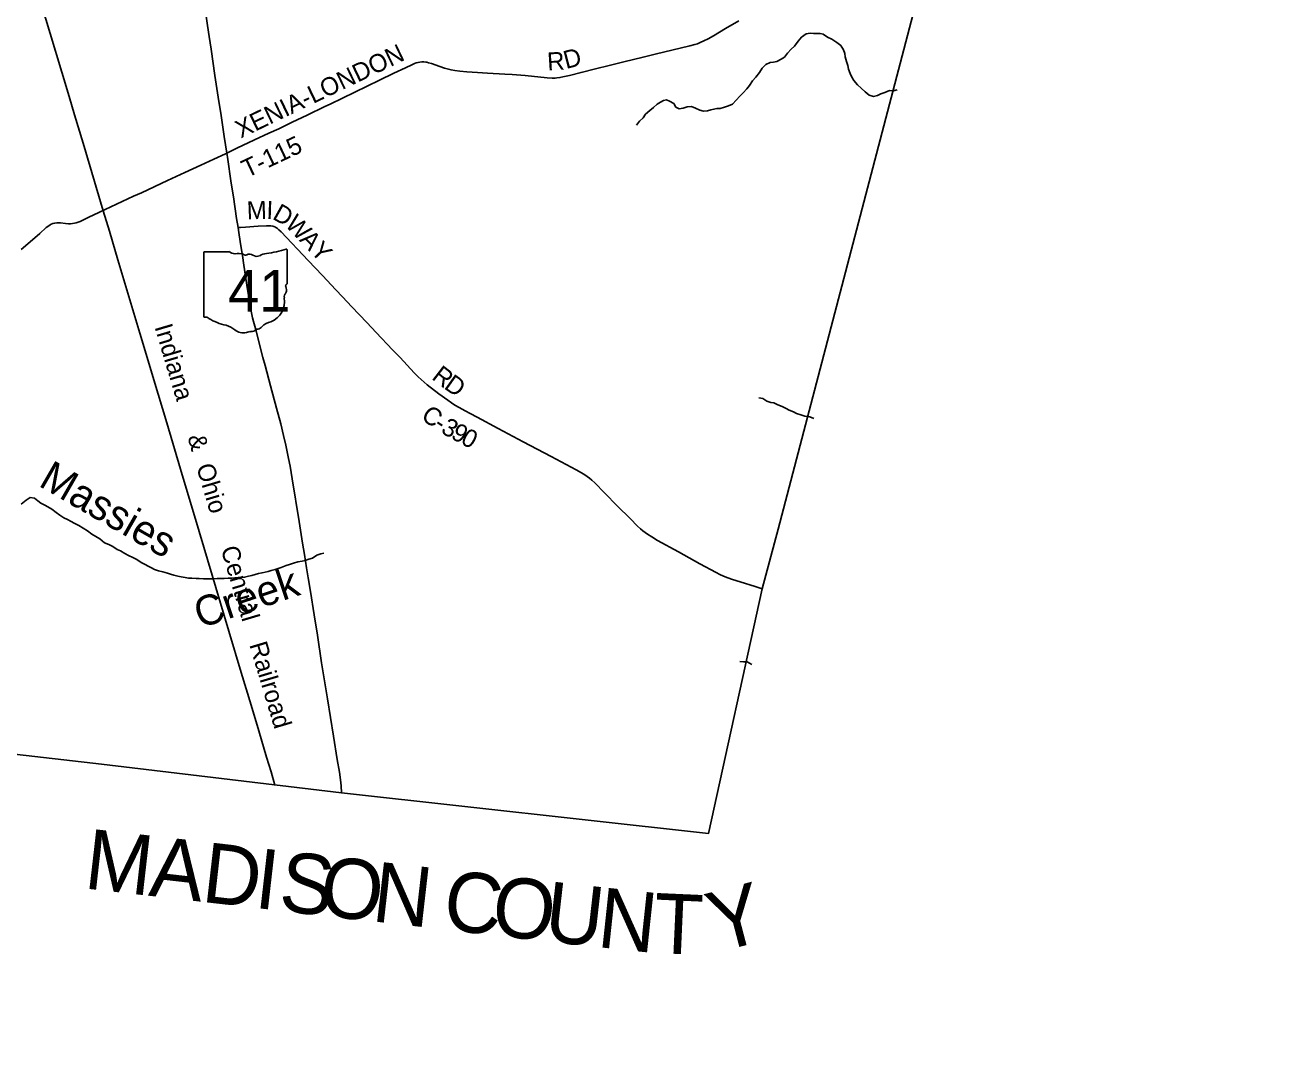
# Model space of a CAD drawing. Extents: x 1410790 to 1770854, y 566777 to 831614.
# Drawn here: x 1651013 to 1671974, y 642079 to 659329 of the extents above; entities that cross this region are included whole.
import ezdxf

# ---------------------------------------------------------------- set-up
doc = ezdxf.new("R2010")
doc.units = 0
for name, color, linetype in [('GM_X_Adjacent_County', 7, 'Continuous'), ('GM_X_Adjacent_County_Text', 7, 'Continuous'), ('GM_X_County', 7, 'Continuous'), ('GM_X_County_Road', 7, 'Continuous'), ('GM_X_County_Road_Text', 7, 'Continuous'), ('GM_X_Minor_River', 7, 'Continuous'), ('GM_X_Minor_River_Text', 7, 'Continuous'), ('GM_X_Rail_Line', 7, 'Continuous'), ('GM_X_Rail_Line_Text', 7, 'Continuous'), ('GM_X_State_Location', 7, 'Continuous'), ('GM_X_State_Route', 7, 'Continuous'), ('GM_X_State_Shield', 7, 'Continuous'), ('GM_X_Township', 7, 'Continuous'), ('GM_X_Township_Road', 7, 'Continuous'), ('GM_X_Township_Road_Text', 7, 'Continuous')]:
    doc.layers.add(name, color=color, linetype=linetype)

msp = doc.modelspace()

# ---------------------------------------------------------------- linework, layer by layer
at = {"layer": 'GM_X_Adjacent_County'}
msp.add_lwpolyline([(1671974, 683181), (1671693, 682151), (1669822, 675181), (1669783, 675026), (1667943, 667921), (1667581, 666498), (1666885, 663874), (1666084, 660564), (1663561, 650929), (1663296, 649933), (1662403, 645855), (1656287, 646528), (1652288, 647008), (1645905, 647740), (1645710, 645966), (1645124, 639449)], dxfattribs=at)
at = {"layer": 'GM_X_County'}
msp.add_lwpolyline([(1671974, 683181), (1671693, 682151), (1669822, 675181), (1669783, 675026), (1667943, 667921), (1667581, 666498), (1666885, 663874), (1666084, 660564), (1663561, 650929), (1663296, 649933), (1662403, 645855), (1656287, 646528), (1652288, 647008), (1645905, 647740), (1646054, 648559), (1644155, 648666), (1640422, 649068), (1640009, 649114), (1636122, 649546)], dxfattribs=at)
at = {"layer": 'GM_X_County_Road'}
msp.add_lwpolyline([(1654561, 655954), (1654601, 655957), (1654683, 655963), (1654897, 655975), (1655035, 655981), (1655081, 655984), (1655110, 655983), (1655143, 655977), (1655159, 655972), (1655174, 655966), (1655189, 655958), (1655203, 655950), (1655217, 655940), (1655242, 655918), (1655278, 655882), (1655729, 655407), (1655966, 655157), (1656191, 654918), (1656300, 654801), (1656459, 654634), (1656707, 654372), (1656865, 654204), (1657134, 653918), (1657261, 653786), (1657497, 653535), (1657565, 653464), (1657612, 653419), (1657661, 653375), (1657711, 653334), (1657907, 653185), (1658056, 653075), (1658118, 653030), (1658173, 652994), (1658244, 652953), (1658344, 652898), (1658431, 652852), (1658547, 652791), (1658896, 652607), (1659315, 652383), (1659778, 652136), (1660199, 651914), (1660286, 651866), (1660341, 651832), (1660382, 651804), (1660421, 651774), (1660459, 651741), (1660507, 651696), (1660669, 651534), (1660887, 651311), (1661096, 651102), (1661221, 650975), (1661269, 650930), (1661308, 650898), (1661347, 650869), (1661387, 650841), (1661457, 650797), (1661554, 650740), (1661900, 650549), (1662259, 650351), (1662530, 650202), (1662589, 650172), (1662653, 650144), (1662727, 650115), (1662804, 650087), (1662929, 650048), (1663179, 649969), (1663296, 649933)], dxfattribs=at)
at = {"layer": 'GM_X_Minor_River'}
for points in [[(1665544, 658249), (1665483, 658236), (1665417, 658237), (1665342, 658207), (1665272, 658182), (1665216, 658158), (1665150, 658142), (1665082, 658159), (1665012, 658215), (1664946, 658278), (1664885, 658336), (1664825, 658406), (1664783, 658471), (1664764, 658523), (1664738, 658595), (1664726, 658655), (1664703, 658724), (1664681, 658802), (1664672, 658856), (1664654, 658918), (1664608, 658989), (1664541, 659037), (1664455, 659094), (1664387, 659130), (1664315, 659177), (1664261, 659187), (1664201, 659187), (1664151, 659190), (1664099, 659194), (1664029, 659184), (1663950, 659127), (1663896, 659061), (1663833, 658981), (1663781, 658931), (1663718, 658862), (1663668, 658794), (1663614, 658760), (1663539, 658722), (1663485, 658713), (1663431, 658705), (1663355, 658671), (1663298, 658609), (1663252, 658540), (1663189, 658464), (1663133, 658402), (1663086, 658320), (1663042, 658266), (1662981, 658198), (1662927, 658147), (1662862, 658077), (1662800, 658011), (1662734, 657981), (1662671, 657960), (1662595, 657938), (1662543, 657938), (1662491, 657927), (1662441, 657917), (1662387, 657903), (1662317, 657893), (1662255, 657912), (1662187, 657946), (1662121, 657973), (1662049, 657965), (1661978, 657947), (1661914, 657934), (1661860, 657962), (1661827, 658022), (1661753, 658061), (1661701, 658081), (1661651, 658074), (1661601, 658046), (1661548, 658010), (1661488, 657958), (1661426, 657904), (1661353, 657843), (1661311, 657783), (1661250, 657727), (1661204, 657663)], [(1664160, 652770), (1664090, 652798), (1664007, 652808), (1663939, 652834), (1663869, 652853), (1663817, 652883), (1663749, 652911), (1663695, 652940), (1663627, 652972), (1663555, 652999), (1663490, 653031), (1663440, 653037), (1663376, 653058), (1663306, 653104), (1663242, 653113)], [(1650945, 651342), (1651028, 651411), (1651097, 651454), (1651167, 651442), (1651223, 651397), (1651274, 651360), (1651350, 651322), (1651458, 651261), (1651532, 651206), (1651593, 651161), (1651657, 651116), (1651717, 651088), (1651779, 651053), (1651832, 651024), (1651910, 650988), (1651980, 650943), (1652052, 650898)], [(1652052, 650898), (1652123, 650843), (1652191, 650805), (1652255, 650764), (1652337, 650700)], [(1652337, 650700), (1652405, 650671), (1652475, 650635), (1652549, 650590), (1652601, 650564), (1652673, 650520), (1652738, 650485), (1652806, 650453), (1652876, 650418), (1652946, 650370), (1653012, 650338), (1653066, 650307), (1653120, 650279), (1653171, 650255), (1653233, 650234), (1653309, 650214), (1653383, 650191), (1653437, 650175), (1653489, 650157), (1653555, 650144), (1653611, 650132), (1653681, 650118), (1653735, 650109), (1653789, 650107), (1653861, 650106), (1653913, 650104), (1653986, 650100), (1654058, 650097), (1654108, 650099), (1654162, 650101), (1654214, 650103), (1654272, 650102), (1654330, 650104), (1654394, 650108), (1654456, 650111), (1654508, 650117), (1654564, 650119), (1654614, 650122), (1654671, 650126), (1654737, 650142), (1654793, 650153), (1654901, 650185), (1654961, 650200), (1655011, 650210), (1655062, 650222), (1655112, 650238), (1655178, 650253), (1655230, 650271), (1655280, 650287), (1655363, 650318), (1655417, 650338), (1655483, 650360), (1655555, 650379), (1655629, 650391), (1655680, 650405), (1655740, 650424), (1655804, 650442), (1655874, 650494), (1655943, 650515), (1655993, 650525)], [(1663123, 648672), (1663046, 648717), (1662984, 648714), (1662924, 648720)]]:
    msp.add_lwpolyline(points, dxfattribs=at)
at = {"layer": 'GM_X_Rail_Line'}
msp.add_lwpolyline([(1655177, 646661), (1655111, 646880), (1655038, 647123), (1654906, 647565), (1654778, 647992), (1654616, 648536), (1654410, 649227), (1653914, 650885), (1653603, 651924), (1653373, 652700), (1653229, 653178), (1652926, 654192), (1652560, 655418), (1652417, 655892), (1652314, 656236), (1651979, 657361), (1651838, 657833), (1651745, 658140), (1651625, 658543), (1651432, 659188), (1651215, 659914)], dxfattribs=at)
at = {"layer": 'GM_X_State_Route'}
msp.add_lwpolyline([(1656287, 646528), (1656278, 646649), (1656268, 646747), (1656250, 646877), (1656215, 647088), (1656152, 647477), (1656102, 647787), (1656052, 648096), (1656004, 648396), (1655954, 648699), (1655883, 649159), (1655829, 649500), (1655766, 649888), (1655730, 650115), (1655702, 650279), (1655668, 650503), (1655637, 650695), (1655578, 651054), (1655464, 651766), (1655429, 651976), (1655404, 652105), (1655356, 652328), (1655319, 652488), (1655272, 652680), (1655200, 652945), (1655102, 653314), (1655012, 653655), (1654977, 653786), (1654902, 654070), (1654861, 654233), (1654818, 654389), (1654802, 654452), (1654783, 654534), (1654769, 654613), (1654750, 654729), (1654719, 654924), (1654658, 655329), (1654633, 655491), (1654602, 655685), (1654567, 655912), (1654561, 655954), (1654537, 656107), (1654485, 656464), (1654449, 656693), (1654385, 657129), (1654374, 657194), (1654330, 657475), (1654278, 657823), (1654232, 658129), (1654177, 658491), (1654111, 658931), (1654080, 659139), (1654051, 659321), (1654011, 659593)], dxfattribs=at)
at = {"layer": 'GM_X_State_Shield'}
for p, q in [((1653989, 655534), (1653989, 654477)), ((1654410, 655552), (1654003, 655552)), ((1655381, 655025), (1655381, 655578)), ((1655381, 655025), (1655381, 655025))]:
    msp.add_line(p, q, dxfattribs=at)
for centre, radius, start, end in [((1654005, 655536), 16.1, 98.1301, 188.1301), ((1654508, 655675), 156, 231.6195, 271.1119), ((1654559, 654959), 562, 80.4867, 94.9883), ((1654687, 655541), 45.1, 219.7921, 297.1024), ((1654753, 655419), 93.8, 54.4667, 119.1411), ((1654874, 655587), 113, 233.8562, 294.8282), ((1655074, 655229), 297, 97.3462, 120.7689), ((1654885, 656992), 1476, 275.8445, 288.9065), ((1655366, 655580), 15.5, 351.8621, 97.738), ((1655437, 654794), 105, 136.8065, 186.9296), ((1655378, 654985), 24, 107.944, 210.337), ((1655225, 654915), 144, 340.033, 23.6496), ((1655365, 655023), 16.6, 289.6038, 7.7341), ((1654968, 654724), 369, 292.3089, 8.9858), ((1654005, 654475), 16.3, 171.9584, 258.3066), ((1654008, 654583), 124, 267.339, 280.6039), ((1654033, 654416), 44.8, 29.7484, 93.2717), ((1654598, 655365), 1066, 240.4129, 257.1985), ((1654280, 654002), 334, 47.1842, 75.836), ((1654641, 654411), 212, 230.7004, 286.2918), ((1654764, 654045), 174, 85.6951, 111.2099), ((1654779, 654332), 113, 268.777, 315.5493), ((1654881, 654229), 31.8, 65.7517, 132.6484), ((1654867, 654375), 119, 282.8732, 323.2771), ((1655124, 654180), 202, 94.4031, 142.5768)]:
    msp.add_arc(centre, radius, start, end, dxfattribs=at)
at = {"layer": 'GM_X_Township'}
msp.add_lwpolyline([(1636122, 649546), (1640009, 649114), (1640422, 649068), (1644155, 648666), (1646054, 648559), (1645905, 647740), (1652288, 647008), (1656287, 646528), (1662403, 645855), (1663296, 649933), (1663561, 650929), (1666084, 660564), (1666885, 663874), (1667581, 666498), (1667943, 667921), (1669783, 675026), (1669822, 675181), (1659011, 676224), (1657686, 676331), (1656836, 676404), (1649879, 677009), (1644674, 677520), (1639318, 678094), (1633970, 678678)], dxfattribs=at)
at = {"layer": 'GM_X_Township_Road'}
for points in [[(1654374, 657194), (1654540, 657278), (1654837, 657416), (1655075, 657527), (1655239, 657603), (1655461, 657709), (1655712, 657828), (1656008, 657971), (1656096, 658014), (1656303, 658114), (1656510, 658213), (1656919, 658411), (1657160, 658526), (1657351, 658619), (1657455, 658669), (1657500, 658688), (1657530, 658699), (1657561, 658708), (1657593, 658714), (1657625, 658717), (1657657, 658717), (1657689, 658714), (1657705, 658711), (1657737, 658703), (1657783, 658688), (1657922, 658638), (1658000, 658611), (1658047, 658598), (1658111, 658582), (1658176, 658571), (1658258, 658562), (1658372, 658552), (1658552, 658540), (1658717, 658531), (1659005, 658512), (1659131, 658504), (1659348, 658489), (1659712, 658453), (1659794, 658447), (1659844, 658447), (1659877, 658449), (1659926, 658456), (1659974, 658465), (1660086, 658492), (1660279, 658541), (1660516, 658598), (1660748, 658658), (1660990, 658717), (1661311, 658796), (1661534, 658850), (1661789, 658911), (1662089, 658982), (1662172, 659004), (1662219, 659020), (1662265, 659038), (1662325, 659065), (1662398, 659103), (1662484, 659151), (1662688, 659273), (1662907, 659401)], [(1650946, 655588), (1651095, 655717), (1651255, 655858), (1651366, 655955), (1651405, 655985), (1651432, 656002), (1651446, 656010), (1651476, 656022), (1651507, 656030), (1651539, 656033), (1651555, 656034), (1651604, 656032), (1651685, 656023), (1651735, 656019), (1651768, 656019), (1651801, 656021), (1651834, 656027), (1651866, 656035), (1651897, 656045), (1651928, 656058), (1652077, 656128), (1652240, 656205), (1652344, 656254), (1652537, 656344), (1652819, 656475), (1652954, 656536), (1653387, 656739), (1653674, 656870), (1653943, 656996), (1654160, 657095), (1654354, 657185), (1654374, 657194)]]:
    msp.add_lwpolyline(points, dxfattribs=at)

# ---------------------------------------------------------------- texts
at = {"layer": 'GM_X_Adjacent_County_Text'}
for s, rotation, p in [('M', 353.4754, (1651976, 644940)), ('A', 353.4752, (1653056, 644817)), ('D', 353.4757, (1653934, 644716)), ('I', 353.4746, (1654813, 644616)), ('S', 353.4756, (1655219, 644569)), ('O', 353.4752, (1655893, 644492)), ('N', 353.4754, (1656771, 644392)), ('C', 353.4751, (1657952, 644257)), ('O', 353.4752, (1658760, 644164)), ('U', 353.4782, (1659639, 644064)), ('Y', 14.6545, (1662545, 643864)), ('N', 353.9084, (1660526, 643962)), ('T', 357.4284, (1661472, 643863))]:
    msp.add_text(s, height=1000, rotation=rotation, dxfattribs=at).set_placement(p)
at = {"layer": 'GM_X_County_Road_Text'}
for s, rotation, p in [('M', 2.26, (1654712, 656088)), ('I', 358.0989, (1655031, 656100)), ('D', 330.852, (1655118, 656106)), ('W', 313.8046, (1655330, 655992)), ('A', 313.6463, (1655571, 655741)), ('Y', 313.6463, (1655753, 655550)), ('R', 322.3417, (1657774, 653439)), ('D', 324.7146, (1657979, 653281)), ('C', 323.6575, (1657594, 652775)), ('3', 330.549, (1657926, 652541)), ('-', 326.6998, (1657805, 652620)), ('9', 331.8882, (1658092, 652448)), ('0', 332.0092, (1658254, 652361))]:
    msp.add_text(s, height=300, rotation=rotation, dxfattribs=at).set_placement(p)
at = {"layer": 'GM_X_Minor_River_Text'}
for s, rotation, p in [('Massies', 330.0261, (1651218, 651656)), ('Creek', 18.5412, (1653931, 649268))]:
    msp.add_text(s, height=500, rotation=rotation, dxfattribs=at).set_placement(p)
at = {"layer": 'GM_X_Rail_Line_Text'}
for s, rotation, p in [('Indiana', 286.584, (1653167, 654300)), ('&', 286.1289, (1653717, 652463)), ('Ohio', 286.5503, (1653862, 651973)), ('Central', 286.5484, (1654271, 650600)), ('Railroad', 286.6557, (1654747, 649002))]:
    msp.add_text(s, height=299, rotation=rotation, dxfattribs=at).set_placement(p)
at = {"layer": 'GM_X_State_Location'}
msp.add_text('41', height=1, rotation=0, dxfattribs=at).set_placement((1654418, 654862))
for s in ['s', 'r']:
    msp.add_text(s, height=1, dxfattribs=at).set_placement((1654669, 654935))
at = {"layer": 'GM_X_State_Shield'}
msp.add_text('41', height=696.1, dxfattribs=at).set_placement((1654396, 654552))
at = {"layer": 'GM_X_Township_Road_Text'}
for s, rotation, p in [('XENIA-LONDON', 25.5734, (1654606, 657437)), ('R', 3.5031, (1659722, 658571)), ('D', 14.626, (1660029, 658596)), ('T-115', 25.2157, (1654711, 656779))]:
    msp.add_text(s, height=300, rotation=rotation, dxfattribs=at).set_placement(p)

doc.saveas('drawing.dxf')
